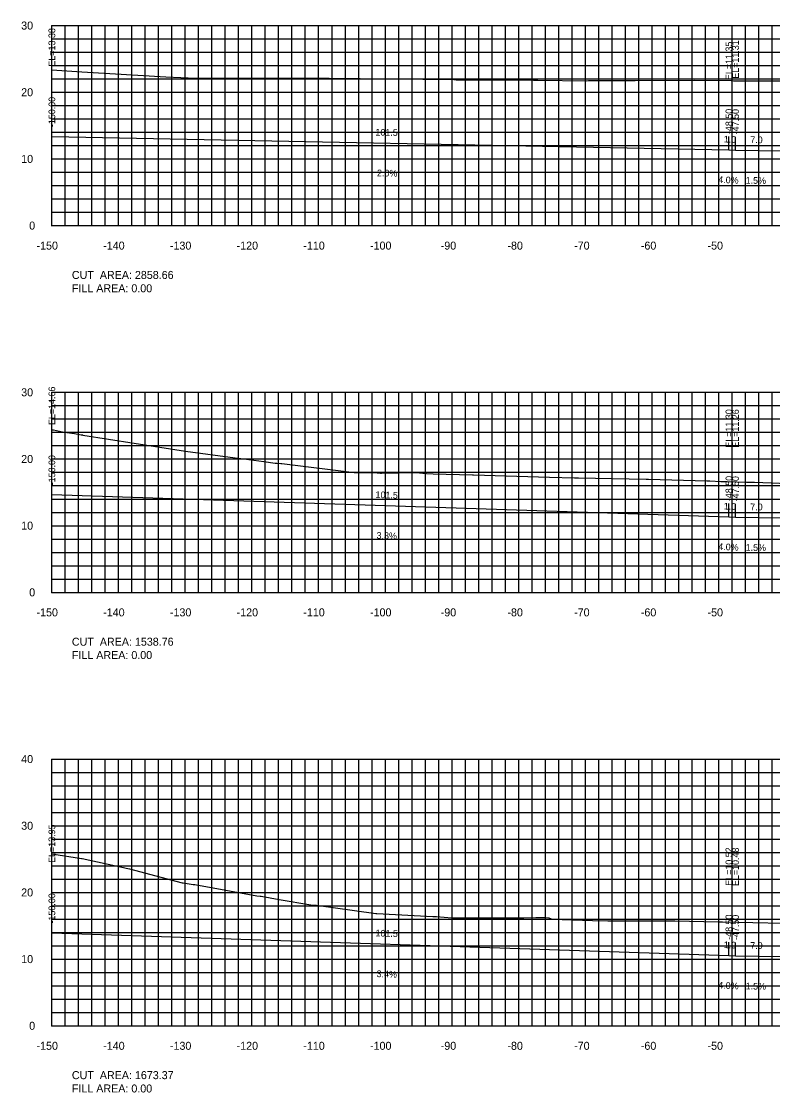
# Model space of a CAD drawing. Extents: x 1797789 to 1803805, y 249066 to 250293.
# Drawn here: x 1802816.4 to 1802929.1, y 250089.4 to 250250 of the extents above; entities that cross this region are included whole.
import ezdxf

# ---------------------------------------------------------------- set-up
doc = ezdxf.new("R2010")
doc.units = 0
for name, color, linetype in [('10', 7, 'Continuous'), ('3', 7, 'Continuous'), ('31', 7, 'Continuous'), ('4', 7, 'Continuous'), ('60', 7, 'Continuous'), ('ANNO-TXT', 7, 'Continuous'), ('CL-CNST', 7, 'Continuous'), ('Level 62', 7, 'Continuous'), ('M-ROADS', 7, 'Continuous')]:
    doc.layers.add(name, color=color, linetype=linetype)

msp = doc.modelspace()

# ---------------------------------------------------------------- linework, layer by layer
for p, q in [((1802821, 250232.81), (1802821, 250234.81)), ((1802922.5, 250230.78), (1802922.5, 250232.78)), ((1802923.5, 250230.74), (1802923.5, 250232.74)), ((1802821, 250179.1), (1802821, 250181.1)), ((1802922.5, 250175.74), (1802922.5, 250177.74)), ((1802923.5, 250175.7), (1802923.5, 250177.7)), ((1802821, 250113.38), (1802821, 250115.38)), ((1802922.5, 250109.96), (1802922.5, 250111.96)), ((1802923.5, 250109.92), (1802923.5, 250111.92))]:
    msp.add_line(p, q)
at = {"layer": '60'}
for p, q in [((1802820.94, 250249.43), (1802821, 250249.43)), ((1802821, 250219.43), (1802821, 250249.43)), ((1802820.94, 250239.43), (1802821, 250239.43)), ((1802820.94, 250229.43), (1802821, 250229.43)), ((1802820.94, 250219.43), (1802821, 250219.43)), ((1802821, 250219.43), (1803121, 250219.43)), ((1802821, 250219.37), (1802821, 250219.43)), ((1802831, 250219.37), (1802831, 250219.43)), ((1802841, 250219.37), (1802841, 250219.43)), ((1802851, 250219.37), (1802851, 250219.43)), ((1802861, 250219.37), (1802861, 250219.43)), ((1802871, 250219.37), (1802871, 250219.43)), ((1802881, 250219.37), (1802881, 250219.43)), ((1802891, 250219.37), (1802891, 250219.43)), ((1802901, 250219.37), (1802901, 250219.43)), ((1802911, 250219.37), (1802911, 250219.43)), ((1802921, 250219.37), (1802921, 250219.43)), ((1802820.94, 250194.43), (1802821, 250194.43)), ((1802821, 250164.43), (1802821, 250194.43)), ((1802820.94, 250184.43), (1802821, 250184.43)), ((1802820.94, 250174.43), (1802821, 250174.43)), ((1802820.94, 250164.43), (1802821, 250164.43)), ((1802821, 250164.43), (1803121, 250164.43)), ((1802821, 250164.37), (1802821, 250164.43)), ((1802831, 250164.37), (1802831, 250164.43)), ((1802841, 250164.37), (1802841, 250164.43)), ((1802851, 250164.37), (1802851, 250164.43)), ((1802861, 250164.37), (1802861, 250164.43)), ((1802871, 250164.37), (1802871, 250164.43)), ((1802881, 250164.37), (1802881, 250164.43)), ((1802891, 250164.37), (1802891, 250164.43)), ((1802901, 250164.37), (1802901, 250164.43)), ((1802911, 250164.37), (1802911, 250164.43)), ((1802921, 250164.37), (1802921, 250164.43)), ((1802820.94, 250139.43), (1802821, 250139.43)), ((1802821, 250099.43), (1802821, 250139.43)), ((1802820.94, 250129.43), (1802821, 250129.43)), ((1802820.94, 250119.43), (1802821, 250119.43)), ((1802820.94, 250109.43), (1802821, 250109.43)), ((1802820.94, 250099.43), (1802821, 250099.43)), ((1802821, 250099.43), (1803121, 250099.43)), ((1802821, 250099.37), (1802821, 250099.43)), ((1802831, 250099.37), (1802831, 250099.43)), ((1802841, 250099.37), (1802841, 250099.43)), ((1802851, 250099.37), (1802851, 250099.43)), ((1802861, 250099.37), (1802861, 250099.43)), ((1802871, 250099.37), (1802871, 250099.43)), ((1802881, 250099.37), (1802881, 250099.43)), ((1802891, 250099.37), (1802891, 250099.43)), ((1802901, 250099.37), (1802901, 250099.43)), ((1802911, 250099.37), (1802911, 250099.43)), ((1802921, 250099.37), (1802921, 250099.43))]:
    msp.add_line(p, q, dxfattribs=at)
at = {"layer": 'CL-CNST'}
for points in [[(1802821, 250232.81), (1802922.5, 250230.78), (1802923.5, 250230.74), (1802930.5, 250230.64), (1802930.5, 250230.64), (1802930.83, 250230.64), (1802931, 250230.14), (1802933, 250230.3), (1802937, 250230.38), (1802971, 250231.13), (1803005, 250230.38), (1803009, 250230.3), (1803011, 250230.14), (1803011.17, 250230.64), (1803011.5, 250230.64), (1803011.5, 250230.64), (1803018.5, 250230.74), (1803019.5, 250230.78), (1803121, 250230.71)], [(1802821, 250179.1), (1802922.5, 250175.74), (1802923.5, 250175.7), (1802930.5, 250175.59), (1802930.5, 250175.59), (1802930.83, 250175.59), (1802931, 250175.09), (1802933, 250175.25), (1802937, 250175.34), (1802971, 250176.09), (1803005, 250175.34), (1803009, 250175.25), (1803011, 250175.09), (1803011.17, 250175.59), (1803011.5, 250175.59), (1803011.5, 250175.59), (1803018.5, 250175.7), (1803019.5, 250175.74), (1803121, 250175.67)], [(1802821, 250113.38), (1802922.5, 250109.96), (1802923.5, 250109.92), (1802930.5, 250109.81), (1802930.5, 250109.81), (1802930.83, 250109.81), (1802931, 250109.31), (1802933, 250109.47), (1802937, 250109.56), (1802971, 250110.31), (1803005, 250109.56), (1803009, 250109.47), (1803011, 250109.31), (1803011.17, 250109.81), (1803011.5, 250109.81), (1803011.5, 250109.81), (1803018.5, 250109.92), (1803019.5, 250109.96), (1803121, 250110.25)]]:
    msp.add_lwpolyline(points, dxfattribs=at)
at = {"layer": 'Level 62'}
for p, q in [((1802821, 250249.43), (1803121, 250249.43)), ((1802821, 250219.43), (1802821, 250249.43)), ((1802823, 250219.43), (1802823, 250249.43)), ((1802825, 250219.43), (1802825, 250249.43)), ((1802827, 250219.43), (1802827, 250249.43)), ((1802829, 250219.43), (1802829, 250249.43)), ((1802831, 250219.43), (1802831, 250249.43)), ((1802833, 250219.43), (1802833, 250249.43)), ((1802835, 250219.43), (1802835, 250249.43)), ((1802837, 250219.43), (1802837, 250249.43)), ((1802839, 250219.43), (1802839, 250249.43)), ((1802841, 250219.43), (1802841, 250249.43)), ((1802843, 250219.43), (1802843, 250249.43)), ((1802845, 250219.43), (1802845, 250249.43)), ((1802847, 250219.43), (1802847, 250249.43)), ((1802849, 250219.43), (1802849, 250249.43)), ((1802851, 250219.43), (1802851, 250249.43)), ((1802853, 250219.43), (1802853, 250249.43)), ((1802855, 250219.43), (1802855, 250249.43)), ((1802857, 250219.43), (1802857, 250249.43)), ((1802859, 250219.43), (1802859, 250249.43)), ((1802861, 250219.43), (1802861, 250249.43)), ((1802863, 250219.43), (1802863, 250249.43)), ((1802865, 250219.43), (1802865, 250249.43)), ((1802867, 250219.43), (1802867, 250249.43)), ((1802869, 250219.43), (1802869, 250249.43)), ((1802871, 250219.43), (1802871, 250249.43)), ((1802873, 250219.43), (1802873, 250249.43)), ((1802875, 250219.43), (1802875, 250249.43)), ((1802877, 250219.43), (1802877, 250249.43)), ((1802879, 250219.43), (1802879, 250249.43)), ((1802881, 250219.43), (1802881, 250249.43)), ((1802883, 250219.43), (1802883, 250249.43)), ((1802885, 250219.43), (1802885, 250249.43)), ((1802887, 250219.43), (1802887, 250249.43)), ((1802889, 250219.43), (1802889, 250249.43)), ((1802891, 250219.43), (1802891, 250249.43)), ((1802893, 250219.43), (1802893, 250249.43)), ((1802895, 250219.43), (1802895, 250249.43)), ((1802897, 250219.43), (1802897, 250249.43)), ((1802899, 250219.43), (1802899, 250249.43)), ((1802901, 250219.43), (1802901, 250249.43)), ((1802903, 250219.43), (1802903, 250249.43)), ((1802905, 250219.43), (1802905, 250249.43)), ((1802907, 250219.43), (1802907, 250249.43)), ((1802909, 250219.43), (1802909, 250249.43)), ((1802911, 250219.43), (1802911, 250249.43)), ((1802913, 250219.43), (1802913, 250249.43)), ((1802915, 250219.43), (1802915, 250249.43)), ((1802917, 250219.43), (1802917, 250249.43)), ((1802919, 250219.43), (1802919, 250249.43)), ((1802921, 250219.43), (1802921, 250249.43)), ((1802923, 250219.43), (1802923, 250249.43)), ((1802925, 250219.43), (1802925, 250249.43)), ((1802927, 250219.43), (1802927, 250249.43)), ((1802929, 250219.43), (1802929, 250249.43)), ((1802821, 250247.43), (1803121, 250247.43)), ((1802821, 250245.43), (1803121, 250245.43)), ((1802821, 250243.43), (1803121, 250243.43)), ((1802821, 250241.43), (1803121, 250241.43)), ((1802821, 250239.43), (1803121, 250239.43)), ((1802821, 250237.43), (1803121, 250237.43)), ((1802821, 250235.43), (1803121, 250235.43)), ((1802821, 250233.43), (1803121, 250233.43)), ((1802821, 250231.43), (1803121, 250231.43)), ((1802821, 250229.43), (1803121, 250229.43)), ((1802821, 250227.43), (1803121, 250227.43)), ((1802821, 250225.43), (1803121, 250225.43)), ((1802821, 250223.43), (1803121, 250223.43)), ((1802821, 250221.43), (1803121, 250221.43)), ((1802821, 250219.43), (1803121, 250219.43)), ((1802821, 250194.43), (1803121, 250194.43)), ((1802821, 250164.43), (1802821, 250194.43)), ((1802823, 250164.43), (1802823, 250194.43)), ((1802825, 250164.43), (1802825, 250194.43)), ((1802827, 250164.43), (1802827, 250194.43)), ((1802829, 250164.43), (1802829, 250194.43)), ((1802831, 250164.43), (1802831, 250194.43)), ((1802833, 250164.43), (1802833, 250194.43)), ((1802835, 250164.43), (1802835, 250194.43)), ((1802837, 250164.43), (1802837, 250194.43)), ((1802839, 250164.43), (1802839, 250194.43)), ((1802841, 250164.43), (1802841, 250194.43)), ((1802843, 250164.43), (1802843, 250194.43)), ((1802845, 250164.43), (1802845, 250194.43)), ((1802847, 250164.43), (1802847, 250194.43)), ((1802849, 250164.43), (1802849, 250194.43)), ((1802851, 250164.43), (1802851, 250194.43)), ((1802853, 250164.43), (1802853, 250194.43)), ((1802855, 250164.43), (1802855, 250194.43)), ((1802857, 250164.43), (1802857, 250194.43)), ((1802859, 250164.43), (1802859, 250194.43)), ((1802861, 250164.43), (1802861, 250194.43)), ((1802863, 250164.43), (1802863, 250194.43)), ((1802865, 250164.43), (1802865, 250194.43)), ((1802867, 250164.43), (1802867, 250194.43)), ((1802869, 250164.43), (1802869, 250194.43)), ((1802871, 250164.43), (1802871, 250194.43)), ((1802873, 250164.43), (1802873, 250194.43)), ((1802875, 250164.43), (1802875, 250194.43)), ((1802877, 250164.43), (1802877, 250194.43)), ((1802879, 250164.43), (1802879, 250194.43)), ((1802881, 250164.43), (1802881, 250194.43)), ((1802883, 250164.43), (1802883, 250194.43)), ((1802885, 250164.43), (1802885, 250194.43)), ((1802887, 250164.43), (1802887, 250194.43)), ((1802889, 250164.43), (1802889, 250194.43)), ((1802891, 250164.43), (1802891, 250194.43)), ((1802893, 250164.43), (1802893, 250194.43)), ((1802895, 250164.43), (1802895, 250194.43)), ((1802897, 250164.43), (1802897, 250194.43)), ((1802899, 250164.43), (1802899, 250194.43)), ((1802901, 250164.43), (1802901, 250194.43)), ((1802903, 250164.43), (1802903, 250194.43)), ((1802905, 250164.43), (1802905, 250194.43)), ((1802907, 250164.43), (1802907, 250194.43)), ((1802909, 250164.43), (1802909, 250194.43)), ((1802911, 250164.43), (1802911, 250194.43)), ((1802913, 250164.43), (1802913, 250194.43)), ((1802915, 250164.43), (1802915, 250194.43)), ((1802917, 250164.43), (1802917, 250194.43)), ((1802919, 250164.43), (1802919, 250194.43)), ((1802921, 250164.43), (1802921, 250194.43)), ((1802923, 250164.43), (1802923, 250194.43)), ((1802925, 250164.43), (1802925, 250194.43)), ((1802927, 250164.43), (1802927, 250194.43)), ((1802929, 250164.43), (1802929, 250194.43)), ((1802821, 250192.43), (1803121, 250192.43)), ((1802821, 250190.43), (1803121, 250190.43)), ((1802821, 250188.43), (1803121, 250188.43)), ((1802821, 250186.43), (1803121, 250186.43)), ((1802821, 250184.43), (1803121, 250184.43)), ((1802821, 250182.43), (1803121, 250182.43)), ((1802821, 250180.43), (1803121, 250180.43)), ((1802821, 250178.43), (1803121, 250178.43)), ((1802821, 250176.43), (1803121, 250176.43)), ((1802821, 250174.43), (1803121, 250174.43)), ((1802821, 250172.43), (1803121, 250172.43)), ((1802821, 250170.43), (1803121, 250170.43)), ((1802821, 250168.43), (1803121, 250168.43)), ((1802821, 250166.43), (1803121, 250166.43)), ((1802821, 250164.43), (1803121, 250164.43)), ((1802821, 250139.43), (1803121, 250139.43)), ((1802821, 250099.43), (1802821, 250139.43)), ((1802823, 250099.43), (1802823, 250139.43)), ((1802825, 250099.43), (1802825, 250139.43)), ((1802827, 250099.43), (1802827, 250139.43)), ((1802829, 250099.43), (1802829, 250139.43)), ((1802831, 250099.43), (1802831, 250139.43)), ((1802833, 250099.43), (1802833, 250139.43)), ((1802835, 250099.43), (1802835, 250139.43)), ((1802837, 250099.43), (1802837, 250139.43)), ((1802839, 250099.43), (1802839, 250139.43)), ((1802841, 250099.43), (1802841, 250139.43)), ((1802843, 250099.43), (1802843, 250139.43)), ((1802845, 250099.43), (1802845, 250139.43)), ((1802847, 250099.43), (1802847, 250139.43)), ((1802849, 250099.43), (1802849, 250139.43)), ((1802851, 250099.43), (1802851, 250139.43)), ((1802853, 250099.43), (1802853, 250139.43)), ((1802855, 250099.43), (1802855, 250139.43)), ((1802857, 250099.43), (1802857, 250139.43)), ((1802859, 250099.43), (1802859, 250139.43)), ((1802861, 250099.43), (1802861, 250139.43)), ((1802863, 250099.43), (1802863, 250139.43)), ((1802865, 250099.43), (1802865, 250139.43)), ((1802867, 250099.43), (1802867, 250139.43)), ((1802869, 250099.43), (1802869, 250139.43)), ((1802871, 250099.43), (1802871, 250139.43)), ((1802873, 250099.43), (1802873, 250139.43)), ((1802875, 250099.43), (1802875, 250139.43)), ((1802877, 250099.43), (1802877, 250139.43)), ((1802879, 250099.43), (1802879, 250139.43)), ((1802881, 250099.43), (1802881, 250139.43)), ((1802883, 250099.43), (1802883, 250139.43)), ((1802885, 250099.43), (1802885, 250139.43)), ((1802887, 250099.43), (1802887, 250139.43)), ((1802889, 250099.43), (1802889, 250139.43)), ((1802891, 250099.43), (1802891, 250139.43)), ((1802893, 250099.43), (1802893, 250139.43)), ((1802895, 250099.43), (1802895, 250139.43)), ((1802897, 250099.43), (1802897, 250139.43)), ((1802899, 250099.43), (1802899, 250139.43)), ((1802901, 250099.43), (1802901, 250139.43)), ((1802903, 250099.43), (1802903, 250139.43)), ((1802905, 250099.43), (1802905, 250139.43)), ((1802907, 250099.43), (1802907, 250139.43)), ((1802909, 250099.43), (1802909, 250139.43)), ((1802911, 250099.43), (1802911, 250139.43)), ((1802913, 250099.43), (1802913, 250139.43)), ((1802915, 250099.43), (1802915, 250139.43)), ((1802917, 250099.43), (1802917, 250139.43)), ((1802919, 250099.43), (1802919, 250139.43)), ((1802921, 250099.43), (1802921, 250139.43)), ((1802923, 250099.43), (1802923, 250139.43)), ((1802925, 250099.43), (1802925, 250139.43)), ((1802927, 250099.43), (1802927, 250139.43)), ((1802929, 250099.43), (1802929, 250139.43)), ((1802821, 250137.43), (1803121, 250137.43)), ((1802821, 250135.43), (1803121, 250135.43)), ((1802821, 250133.43), (1803121, 250133.43)), ((1802821, 250131.43), (1803121, 250131.43)), ((1802821, 250129.43), (1803121, 250129.43)), ((1802821, 250127.43), (1803121, 250127.43)), ((1802821, 250125.43), (1803121, 250125.43)), ((1802821, 250123.43), (1803121, 250123.43)), ((1802821, 250121.43), (1803121, 250121.43)), ((1802821, 250119.43), (1803121, 250119.43)), ((1802821, 250117.43), (1803121, 250117.43)), ((1802821, 250115.43), (1803121, 250115.43)), ((1802821, 250113.43), (1803121, 250113.43)), ((1802821, 250111.43), (1803121, 250111.43)), ((1802821, 250109.43), (1803121, 250109.43)), ((1802821, 250107.43), (1803121, 250107.43)), ((1802821, 250105.43), (1803121, 250105.43)), ((1802821, 250103.43), (1803121, 250103.43)), ((1802821, 250101.43), (1803121, 250101.43)), ((1802821, 250099.43), (1803121, 250099.43))]:
    msp.add_line(p, q, dxfattribs=at)
at = {"layer": 'M-ROADS'}
for points in [[(1802821, 250242.78), (1802825.5, 250242.51), (1802838.1, 250241.72), (1802842.59, 250241.54), (1802842.7, 250241.56), (1802842.89, 250241.55), (1802843.18, 250241.54), (1802843.25, 250241.55), (1802861.57, 250241.52), (1802861.64, 250241.52), (1802861.66, 250241.52), (1802862, 250241.52), (1802862.24, 250241.52), (1802862.55, 250241.53), (1802881.26, 250241.32), (1802881.32, 250241.33), (1802881.63, 250241.3), (1802884.4, 250241.27), (1802884.71, 250241.29), (1802885.21, 250241.31), (1802893.22, 250241.25), (1802893.6, 250241.23), (1802893.85, 250241.22), (1802901.19, 250241.16), (1802901.43, 250241.18), (1802907.88, 250241.21), (1802908.09, 250241.2), (1802908.45, 250241.18), (1802917.4, 250241.25), (1802922.83, 250241.17), (1802923.21, 250241.15), (1802923.41, 250241.14), (1802931.21, 250241.16)], [(1802821, 250188.82), (1802821.24, 250188.78), (1802822.59, 250188.5), (1802822.85, 250188.46), (1802824.41, 250188.24), (1802825.39, 250188.06), (1802825.39, 250188.06), (1802825.61, 250188.03), (1802825.62, 250188.02), (1802841.02, 250185.59), (1802848.48, 250184.6), (1802848.9, 250184.55), (1802849.77, 250184.46), (1802852.79, 250184.05), (1802854.48, 250183.81), (1802854.72, 250183.78), (1802855.34, 250183.74), (1802855.48, 250183.74), (1802866.34, 250182.42), (1802866.64, 250182.42), (1802866.76, 250182.42), (1802869.77, 250182.33), (1802870.25, 250182.32), (1802870.4, 250182.32), (1802875.49, 250182.39), (1802875.56, 250182.4), (1802877.16, 250182.26), (1802878.16, 250182.21), (1802884.06, 250182.07), (1802884.2, 250182.07), (1802895.62, 250181.69), (1802899.35, 250181.6), (1802899.51, 250181.6), (1802899.94, 250181.59), (1802910.09, 250181.41), (1802910.47, 250181.41), (1802919.22, 250181.14), (1802919.65, 250181.13), (1802921.3, 250181.07), (1802922.24, 250181.05), (1802925.12, 250180.96), (1802925.15, 250180.96), (1802926.29, 250180.94), (1802926.34, 250180.94), (1802931.33, 250180.76)], [(1802821, 250125.24), (1802825.43, 250124.51), (1802825.56, 250124.52), (1802831.74, 250123.15), (1802832.12, 250123.08), (1802832.62, 250122.99), (1802840.54, 250120.87), (1802840.7, 250120.87), (1802842.16, 250120.62), (1802842.42, 250120.62), (1802851.71, 250118.94), (1802852.22, 250118.89), (1802852.4, 250118.86), (1802855.09, 250118.35), (1802859.83, 250117.58), (1802860.33, 250117.54), (1802860.67, 250117.51), (1802869.58, 250116.27), (1802869.74, 250116.27), (1802878.14, 250115.8), (1802878.57, 250115.8), (1802878.65, 250115.8), (1802880.97, 250115.63), (1802891.24, 250115.6), (1802891.63, 250115.62), (1802891.76, 250115.61), (1802893.54, 250115.66), (1802894.26, 250115.65), (1802894.75, 250115.65), (1802894.85, 250115.65), (1802895.53, 250115.64), (1802895.99, 250115.41), (1802902.04, 250115.24), (1802904.34, 250115.18), (1802904.43, 250115.18), (1802907.29, 250115.15), (1802907.52, 250115.15), (1802908.76, 250115.15), (1802914.19, 250115.15), (1802914.41, 250115.16), (1802920.94, 250115.04), (1802921.15, 250115.04), (1802921.53, 250115.04), (1802930.63, 250114.84)]]:
    msp.add_lwpolyline(points, dxfattribs=at)

# ---------------------------------------------------------------- texts
at = {"layer": '10'}
for s, p in [('-150', (1802818.7, 250215.83)), ('-140', (1802828.7, 250215.83)), ('-130', (1802838.7, 250215.83)), ('-120', (1802848.7, 250215.83)), ('-110', (1802858.7, 250215.83)), ('-100', (1802868.7, 250215.83)), ('-90', (1802879.3, 250215.83)), ('-80', (1802889.3, 250215.83)), ('-70', (1802899.3, 250215.83)), ('-60', (1802909.3, 250215.83)), ('-50', (1802919.3, 250215.83)), ('-150', (1802818.7, 250160.83)), ('-140', (1802828.7, 250160.83)), ('-130', (1802838.7, 250160.83)), ('-120', (1802848.7, 250160.83)), ('-110', (1802858.7, 250160.83)), ('-100', (1802868.7, 250160.83)), ('-90', (1802879.3, 250160.83)), ('-80', (1802889.3, 250160.83)), ('-70', (1802899.3, 250160.83)), ('-60', (1802909.3, 250160.83)), ('-50', (1802919.3, 250160.83)), ('-150', (1802818.7, 250095.83)), ('-140', (1802828.7, 250095.83)), ('-130', (1802838.7, 250095.83)), ('-120', (1802848.7, 250095.83)), ('-110', (1802858.7, 250095.83)), ('-100', (1802868.7, 250095.83)), ('-90', (1802879.3, 250095.83)), ('-80', (1802889.3, 250095.83)), ('-70', (1802899.3, 250095.83)), ('-60', (1802909.3, 250095.83)), ('-50', (1802919.3, 250095.83))]:
    msp.add_text(s, height=1.2, dxfattribs=at).set_placement(p)
at = {"layer": '3'}
for s, p in [('EL=13.38', (1802821.5, 250243.28)), ('EL=11.35', (1802923, 250241.25)), ('EL=11.31', (1802924, 250241.46)), ('-150.00', (1802821.5, 250234.2)), ('-48.50', (1802923, 250233.16)), ('-47.50', (1802924, 250233.12)), ('EL=14.66', (1802821.5, 250189.52)), ('EL=11.30', (1802923, 250186.13)), ('EL=11.26', (1802924, 250186.12)), ('-150.00', (1802821.5, 250180.48)), ('-48.50', (1802923, 250178.11)), ('-47.50', (1802924, 250178.07)), ('EL=13.95', (1802821.5, 250123.86)), ('EL=10.52', (1802923, 250120.43)), ('EL=10.48', (1802924, 250120.39)), ('-150.00', (1802821.5, 250114.77)), ('-48.50', (1802923, 250112.33)), ('-47.50', (1802924, 250112.29))]:
    msp.add_text(s, height=1, rotation=90, dxfattribs=at).set_placement(p)
at = {"layer": '31'}
for s, p in [('30', (1802816.4, 250248.83)), ('20', (1802816.4, 250238.83)), ('10', (1802816.4, 250228.83)), ('0', (1802817.6, 250218.83)), ('30', (1802816.4, 250193.83)), ('20', (1802816.4, 250183.83)), ('10', (1802816.4, 250173.83)), ('0', (1802817.6, 250163.83)), ('40', (1802816.4, 250138.83)), ('30', (1802816.4, 250128.83)), ('20', (1802816.4, 250118.83)), ('10', (1802816.4, 250108.83)), ('0', (1802817.6, 250098.83))]:
    msp.add_text(s, height=1.2, dxfattribs=at).set_placement(p)
at = {"layer": '4'}
for s, rotation, p in [('101.5', 358.8544, (1802869.5, 250232.94)), ('1.0', 357.7094, (1802921.72, 250231.91)), ('7.0', 359.1406, (1802925.7, 250231.81)), ('2.0%', 358.8544, (1802869.74, 250226.83)), ('4.0%', 357.7094, (1802920.89, 250225.84)), ('1.5%', 359.1406, (1802925.01, 250225.72)), ('101.5', 358.1042, (1802869.51, 250178.59)), ('1.0', 357.7094, (1802921.72, 250176.87)), ('7.0', 359.1406, (1802925.7, 250176.76)), ('3.3%', 358.1042, (1802869.67, 250172.48)), ('4.0%', 357.7094, (1802920.89, 250170.8)), ('1.5%', 359.1406, (1802925.01, 250170.67)), ('101.5', 358.0665, (1802869.51, 250112.85)), ('1.0', 357.7094, (1802921.72, 250111.09)), ('7.0', 359.1406, (1802925.7, 250110.98)), ('3.4%', 358.0665, (1802869.67, 250106.74)), ('4.0%', 357.7094, (1802920.89, 250105.02)), ('1.5%', 359.1406, (1802925.01, 250104.89))]:
    msp.add_text(s, height=1, rotation=rotation, dxfattribs=at).set_placement(p)
at = {"layer": '60'}
for p in [(1802821, 250219.43), (1802821, 250164.43), (1802821, 250099.43)]:
    msp.add_text('-', height=0.0001, dxfattribs=at).set_placement(p)
at = {"layer": 'ANNO-TXT'}
for s, p in [('CUT  AREA: 2858.66', (1802824, 250211.43)), ('FILL AREA: 0.00', (1802824, 250209.43)), ('CUT  AREA: 1538.76', (1802824, 250156.43)), ('FILL AREA: 0.00', (1802824, 250154.43)), ('CUT  AREA: 1673.37', (1802824, 250091.43)), ('FILL AREA: 0.00', (1802824, 250089.43))]:
    msp.add_text(s, height=1.2, dxfattribs=at).set_placement(p)

doc.saveas('drawing.dxf')
